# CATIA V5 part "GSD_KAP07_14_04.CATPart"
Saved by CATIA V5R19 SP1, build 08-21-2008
Part number: GSD_KAP07_14_04
Definition: Beispielmodell für die Funktion Formverrundung / Shape Fillet.
Description: CATIA V5 Flächenmodellierung  Copyright (c) 2009 Maik Hertha IT Consultants
Bounding box of the stored display mesh (mm): x -25 to 45, y -23 to 60, z -21.331 to 45
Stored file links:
  \GSD_BUCH_UEBUNG\GSD_KAP07_14_04.CATPart
  \XV5_ABNAHME_1.0\XV5_BLEND_FILLET_01.CATPart
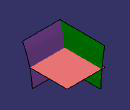
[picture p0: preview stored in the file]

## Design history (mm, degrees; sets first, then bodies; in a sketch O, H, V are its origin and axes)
AxisSystem1 "Absolute Axis System": origin (0, 0, 0), X (1, 0, 0), Y (0, 1, 0), Z (0, 0, 1)
Set1 "Basis_Flaechen"
  Plane1: type Equation, A 0, B 0, C 1, Length 10
  Point1: type OnPlane, Support Plane1, Direction (1, 0, 0), H 10, V -10
  Plane2: type Equation, A 1, B 0, C 0, Length 10
  Plane3: type Equation, A 0, B 1, C 0, Length 0
  Sketch1 on Plane1, origin (10, -10, 10), H (0, 1, 0), V (-1, 0, 0)
    line L1 (0, 35) -> (70, 35)
    line L2 (70, 35) -> (70, -35)
    line L3 (70, -35) -> (0, -35)
    line L4 (0, -35) -> (0, 35)
    curve C1
    construction line L5 (93.4795, 0) -> (-28.9576, 0)
    point P5 (93.4795, 0)
    length L3 = 70
    length L2 = 70 {= Sketch1.length(L3)}
    horizontal: L1 H, L3 H, L5 H
    vertical: L2 V, L4 V
    coincidence: P5 H
    symmetry: L1 L3 L5
  Sketch2 on Plane2, origin (10, -10, 10), H (0, 1, 0), V (0, 0, 1)
    spline S1 through (-12.6316, 35) (-0.0027, 3.7447) (5.7378, -31.331)
    curve C1
    construction line L1 (-28.3244, 0) -> (83.7309, 0)
    point P1 (-28.3244, 0)
    point P3 (-12.6316, 35)
    distance L1 P3 = 35
    coincidence: P1 H
    horizontal: L1 H
  Split1: ToCut Plane1, Cutting Sketch1.C1
  Extrude1: Lim1 35, Lim2 35, Element1 Sketch2.C1, Direction Plane2
  Sketch3 on Plane3, origin (10, 0, 10), H (-1, 0, 0), V (0, 0, 1)
    spline S1 through (26.9876, -31.1238) (28.765, -3.6881) (34.2216, 35)
    curve C1
    point P1 (34.2216, 35)
    distance P1 H = 35
  Extrude2: Lim1 60, Lim2 23, Element1 Sketch3.C1, Direction Plane3
Set2 "Formverrundung"
  DatumSurface1 to DatumSurface3: linked copy from another document
Body1 (main body)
